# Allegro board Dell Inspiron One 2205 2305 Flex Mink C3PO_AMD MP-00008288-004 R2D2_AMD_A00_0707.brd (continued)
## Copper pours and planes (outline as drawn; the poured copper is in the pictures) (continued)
VDD_PCIE on BOTTOM: 56.02,153.42 55.64,153.8 53.73,153.8 53.73,156.21 51.57,158.37 51.57,160.34 52.08,160.85 52.78,160.85 54.37,159.26 54.37,158.12 56.4,156.08 56.4,155.57 56.91,155.07 56.91,154.31 57.41,153.8 57.41,153.54 57.29,153.42
VDD_PCIE on BOTTOM: 57.86,145.92 54.18,145.92 52.91,144.65 48.91,144.65 46.94,146.62 43.13,146.62 42.11,145.61 40.52,145.61 40.52,144.46 41.48,144.46 42.43,143.51 42.43,142.68 42.62,142.49 44.71,142.49 45.48,143.26 47.25,143.26 48.91,141.6 52.08,141.6 54.11,143.64 55.95,143.64 56.46,143.13 58.56,143.13 59.57,144.15 59.83,144.15 59.95,144.27 59.95,145.1 59.7,145.35 58.37,145.35 57.83,145.89 ; 1 cut-out
VDDA18PCIE on TOP: 61.06,129.91 61.48,129.49 61.48,128.02 60.44,126.97 59.8,126.97 59.64,127.14 59.64,129.71 59.84,129.91
VDDA18PCIE on TOP: 59.75,139.45 59.75,141.91 59.95,142.11 59.95,142.34 60.39,142.77 60.39,143.84 60.18,144.04 59.7,144.04 59.32,143.66 59.32,142.72 59.42,142.62 59.42,142.44 58.86,141.88 58.86,139.8 59.07,139.6 59.07,139.4 59.32,139.14 59.32,137.86 59.38,137.79 59.64,137.79 59.76,137.92 59.76,139.43
VDDA18PCIE on BOTTOM: 59.24,127.38 58.68,127.94 58.68,132.54 59.62,133.48 59.62,134.9 59.12,135.41 59.12,136.7 59.03,136.79 59.03,137.58 58.81,137.81 58.81,140.59 58.99,140.77 58.99,141.76 59.4,142.16 59.4,143.65 59.54,143.79 60.06,143.79 60.08,143.76 60.08,142.24 61.86,140.46 61.86,133.48 60.29,131.9 60.29,130.48 61.35,129.41 61.35,128.02 60.72,127.38
VDDAN_P1V1_CLK on TOP: 90.83,69.53 90.54,69.82 90.54,70.56 89.96,71.14 89.96,71.52 90.06,71.62 90.31,71.62 90.53,71.84 90.72,71.84 90.95,71.62 91.3,71.62 91.85,71.07 91.85,70.43 91.83,70.41 91.72,70.28 91.65,70.13 91.64,70.09 91.64,70.06 91.54,69.96 91.4,69.82 91.34,69.63 91.31,69.56 91.24,69.53
VDDAN_P1V1_CLK on TOP: 84.47,87.12 86.62,87.12 86.88,86.87 87.64,86.87 88.02,86.49 88.02,81.47 87.83,81.28 86.88,81.28 86.34,81.82 86.34,84.49 85.86,84.96 84.59,84.96 84.08,85.47 84.08,86.74
VDDAN_P1V1_CLK on BOTTOM: 86.18,85.47 86.18,84.71 86.69,84.2 86.69,82.49 87.07,82.11 87.83,82.11 88.02,82.3 88.02,84.26 88.21,84.45 88.21,84.96 88.02,85.15 88.02,85.22 87.58,85.66 86.37,85.66
VDDAN_P1V1_PCIE on TOP: 96.74,76.96 96.74,75.46 96.4,75.12 96.16,74.88 96.16,74.47 96.29,74.34 97.19,74.34 97.63,73.9 97.65,73.9 98.09,74.34 98.18,74.34 98.26,74.42 98.26,74.85 97.72,75.39 97.72,76.76 98.93,77.98 98.93,80.39 98.31,81.02 98.31,83.06 98.56,83.31 99.45,83.31 100.21,84.07 100.21,85.34 99.97,85.59 98.05,85.59 97.17,84.71 97.17,83.7 95.32,81.85 95.32,78.38
VDDAN_P1V1_PCIE on BOTTOM: 96.7,76.49 96.7,74.25 96.91,74.04 96.91,70.99 97.36,70.55 97.67,70.55 98.12,71 98.12,77.35 97.97,77.51 97.72,77.51
VDDAN_P1V1_SATA on TOP: 101.79,68.12 102.86,68.12 104.58,69.85 109.8,69.85 110.82,68.83 115.96,68.83 116.72,69.6 118.12,69.6 118.5,69.98 119.9,69.98 120.03,69.85 120.03,68.2 119.52,67.69 113.55,67.69 110.12,64.26 109.18,64.26 106.82,66.62 103.72,66.62 103.39,66.29 102.23,66.29 101.86,66.66 101.85,66.66 101.53,66.98 101.53,67.87
VDDAN_P3V3_USB_S on TOP: 78.57,74.42 83.09,69.9 87.06,69.9 87.74,69.21 87.77,69.21 87.9,69.08 87.9,68.9 87.87,68.86 87.76,68.71 87.72,68.53 87.13,67.94 81.8,67.94 80.4,69.34 80.4,69.98 80.15,70.23 77.86,70.23 77.73,70.36 77.73,72.01 76.59,73.15 75.96,73.15 75.83,73.28 75.83,74.17 76.08,74.42
VDDCR_P1V1 on VCC (solid shape): 97.42,69.01 97.42,68.62 97.36,68.5 97.36,64.59 96.64,63.88 93.75,63.88 93.18,64.45 91.97,64.45 91.9,64.53 91.9,65.45 92.4,65.96 92.4,66.72 92.67,66.99 93.56,66.99 94.31,67.74 94.31,68.19 94.83,68.71 95.28,69.15 97.28,69.15
VDDCR_P1V1 on BOTTOM: 93.53,64.26 93.26,64.53 93.26,67.41 93.67,67.82 94.31,67.82 94.63,68.14 95.58,68.14 96.02,68.58 96.02,69.34 96.15,69.47 96.72,69.47 96.91,69.28 96.91,68.58 97.05,68.44 97.94,68.44 98.12,68.25 98.12,66.16 98.27,66.02 98.27,65.22 98.12,65.08 97.43,65.08 97.19,64.84 97.19,63.84 96.98,63.63 96.06,63.63 95.42,64.26
VDDHTRX on TOP: 71.58,172.47 73.1,172.47 73.23,172.34 73.23,171.04 72.75,170.56 72.75,167.04 73.8,165.99 73.8,161.23 71,158.43 71,157.58 70.22,156.79 70.22,155.85 66.56,152.2 66.25,152.2 66.1,152.35 66.1,152.65 69.81,156.36 69.81,157.23 70.14,157.56 70.14,158.09 70.31,158.25 70.31,159.26 72.63,161.58 72.63,163.25 71.18,164.69 71.18,172.07
VDDHTTX on BOTTOM: 72.45,133.18 70.24,135.38 70.24,138.94 69.99,139.19 66.81,139.19 65.16,140.84 65.16,145.29 64.91,145.54 64.91,147.57 65.57,148.23 65.95,148.23 66.15,148.03 66.15,147.62 65.8,147.27 65.8,145.85 67.22,144.42 67.22,144.07 68.34,142.95 68.57,142.95 68.82,142.7 68.82,142.47 69.12,142.16 69.33,142.16 70.42,141.07 70.42,140.61 70.65,140.39 71.23,140.39 71.83,139.79 71.83,139.48 72.3,139.01 72.43,139.01 72.63,138.81 72.63,137.24 75.04,134.82 84.77,134.82 84.91,134.68 84.91,131.76 84.59,131.44 83.83,131.44 83.83,132.33 83.68,132.48 80.42,132.48 79.83,133.07 77.27,133.07 77.16,133.18
VDDIO_P3V3_GBE_S on TOP: 93.33,62.17 93.93,62.17 94.43,62.67 94.43,63.17 94.13,63.47 93.93,63.47 93.13,62.67 93.13,62.37
VDDIO_P3V3_S on TOP: 85.79,70.69 86.93,70.69 87.06,70.56 87.06,70.19 86.82,69.96 84.36,69.96 84.36,69.95 83.68,69.95 78.85,74.78 73.57,74.78 73.16,75.18 73.16,75.95 73.42,76.2 79.51,76.2 79.89,75.82 80.02,75.82 81.54,74.3 81.54,74.17 83.7,72.01 83.7,71.5 84.29,70.92 85.56,70.92
VDDPL_P3V3_SATA on TOP: 102.13,65.77 101.73,65.77 101.13,65.17 101.13,64.87 101.43,64.57 101.73,64.57 102.33,65.17 102.33,65.57
VDDPL_P3V3_USB_S on BOTTOM: 84.72,71.12 84.85,70.99 84.85,70.61 84.72,70.48 81.54,70.48 81.29,70.74 81.29,71.37 81.42,71.5 83.45,71.5 83.83,71.12
VIN_19 on TOP: 162.19,23.37 159.97,23.37 157.94,21.34 157.94,17.91 159.52,16.32 159.52,10.86 159.65,10.73 161.55,10.73 161.94,11.11 161.94,17.84 162.38,18.29 162.38,23.18
CLK_VDD on TOP (solid shape): 37.54,104.08 37.54,103 37.73,102.81 37.73,101.85 36.84,101.85 36.08,102.62 35.06,102.62 34.68,102.23 33.16,102.23 32.78,102.62 26.36,102.62 26.05,102.3 26.05,100.97 26.49,100.52 26.49,97.79 27.44,96.84 30.24,96.84 30.49,96.58 30.49,95.25 27.06,95.25 25.66,96.65 25.66,100.08 25.22,100.52 25.22,103.7 25.66,104.14 37.48,104.14
CPU_M_VREF_SUS on TOP (solid shape): 115.96,183.41 115.96,182.3 115.48,181.81 113.47,181.81 113.12,182.17 113.12,183.59 113.4,183.87 115.5,183.87
CPU_M_VREF_SUS on BOTTOM (solid shape): 115.96,183.54 115.96,179.91 115.71,179.65 115.05,179.65 114.87,179.83 114.87,181.58 114.73,181.72 113.74,181.72 113.35,182.12 113.35,183.41 113.75,183.82 115.68,183.82
CPU_VCORE on BOTTOM (solid shape): outline of 81 points within 123.88,142.3 126.97,160.75
CPU_VCORE on BOTTOM (solid shape): 113.18,159.49 113.25,159.47 113.38,159.33 113.38,158.81 114.27,157.92 114.27,157.67 113.38,156.78 113.38,156.27 114.16,155.49 114.16,155.01 113.38,154.24 113.38,153.73 114.27,152.84 114.27,152.59 113.38,151.7 113.38,151.19 114.18,150.39 114.18,149.96 113.38,149.16 113.38,148.65 114.27,147.76 114.27,147.51 113.38,146.62 113.38,146.11 114.19,145.3 114.19,144.89 113.26,143.95 112.24,143.95 111.86,144.33 111.26,144.33 111.22,144.37 111.22,145.78 111.26,145.86 111.34,145.88 111.98,146.36 111.34,146.84 111.26,146.87 111.22,146.94 111.22,148.32 111.26,148.4 111.34,148.42 111.96,148.76 111.62,149.38 111.6,149.39 111.57,149.42 111.31,149.42 111.31,150.85 111.34,150.92 111.42,150.94 111.98,151.48 111.34,151.92 111.26,151.95 111.22,152.02 111.22,153.4 111.26,153.48 111.34,153.5 111.98,153.98 111.34,154.46 111.26,154.49 111.22,154.56 111.22,155.94 111.26,156.02 111.34,156.04 111.98,156.52 111.34,157 111.26,157.03 111.22,157.1 111.22,158.52 111.26,158.55 111.48,158.55 111.54,158.55 111.86,158.55 112.48,159.18 112.5,159.18 112.67,159.23 112.82,159.33 112.97,159.38 113.11,159.47
CPU_VCORE on BOTTOM (solid shape): outline of 452 points within 116.3,142.3 121.89,160.97
CPU_VCORE on VCC (solid shape): 108.47,181.59 108.47,166.48 108.58,166.37 112.88,162.08 114.77,162.08 114.77,162.07 115.39,162.07 115.39,162.08 116.26,162.08 116.56,162.08 117.72,160.92 122.9,160.92 124.02,162.04 127.22,162.04 128.61,163.44 129.62,163.44 131.02,162.04 132.06,162.04 132.51,161.59 132.51,159.12 132.05,158.66 130.54,158.66 129.79,157.91 129.79,142.67 129.24,142.13 116.16,142.13 115.12,142.11 110.1,137.1 107.65,137.1 105.55,134.99 104.48,134.99 103.79,134.3 81.31,134.3 80.67,134.94 74.38,134.94 73.1,136.22 73.1,137.7 65.96,144.86 65.96,151.71 70.18,155.93 70.18,156.64 70.81,157.27 70.81,158.54 71.72,159.45 73.5,159.45 75.64,161.59 75.64,164.77 76.04,165.16 79.97,165.16 80.97,166.16 80.97,179.25 83.53,181.8 108.26,181.8
CPU_VCORE on TOP: 92.04,165.94 81.57,165.94 80.99,166.52 80.99,179.9 82.65,181.56 106.36,181.56 107.44,180.48 107.44,176.57 105.44,174.57 97.42,174.57 93.81,170.97 93.81,167.72
CPU_VCORE on BOTTOM: 80.85,177.5 80.85,178.94 83.39,181.48 103.01,181.48 103.52,180.97 103.52,177.61 102.63,176.72 101.42,176.72 94.82,170.12 94.82,166.69 93.99,165.86 82.43,165.86 81.37,166.93 81.37,169.8 81.82,170.26 81.82,176.52
CPU_VCORE on BOTTOM: 132.05,161.5 132.01,161.49 131.77,161.37 131.67,161.12 131.67,161.09 131.46,160.88 131.44,160.88 131.22,160.75 131.1,160.53 131.09,160.52 130.71,160.13 129.72,160.13 129.65,160.06 129.65,160.06 129.52,159.93 129.52,158.94 129.44,158.86 128.35,158.86 128.2,159.02 128.2,159.65 128.36,159.81 128.36,162.23 128.06,162.53 128.06,163.07 128.32,163.32 129.68,163.32 130.19,162.81 130.19,162.43 130.57,162.05 131.73,162.05 132.05,161.73
CPU_VCORE on INT1: 108.58,166.37 112.88,162.08 114.77,162.08 114.77,162.07 115.39,162.07 115.39,162.08 116.26,162.08 116.56,162.08 117.72,160.92 122.9,160.92 124.02,162.04 127.22,162.04 128.61,163.44 129.62,163.44 131.02,162.04 132.06,162.04 132.51,161.59 132.51,159.12 132.05,158.66 130.54,158.66 129.79,157.91 129.79,142.67 129.24,142.13 116.16,142.13 115.12,142.11 110.1,137.1 107.65,137.1 105.55,134.99 104.48,134.99 103.79,134.3 81.31,134.3 80.67,134.94 74.38,134.94 73.1,136.22 73.1,137.7 65.96,144.86 65.96,151.71 69.91,155.66 73.24,155.66 75.64,158.05 75.64,164.77 76.04,165.16 79.97,165.16 80.97,166.16 80.97,179.25 83.53,181.8 108.26,181.8 108.47,181.59 108.47,166.48 ; 1 cut-out
CPU_VDDA_RUN_OUT on TOP: 138.12,234.95 138.12,230.38 135.71,230.38 135.46,230.63 135.46,233.62 135.65,233.81 135.71,233.81 136.85,234.95
DCIN on VCC (solid shape): outline of 85 points within 143.33,4.7 149.17,14.92
DCIN on TOP: 144.73,4.83 143.84,5.71 136.54,5.71 134.63,7.62 134.63,10.67 136.15,12.19 137.68,12.19 138.06,12.57 138.06,14.1 138.31,14.35 141.49,14.35 141.74,14.1 143.9,14.1 144.98,15.18 146.46,15.18 147.34,16.06 147.34,17.64 146.12,18.86 146.12,21.46 148.22,23.56 152.41,23.56 153.68,24.83 157.24,24.83 157.24,20.07 156.98,19.81 154.95,19.81 153.76,18.62 153.76,16.94 152.66,15.85 152.66,13.78 152.28,13.4 150.7,13.4 150.38,13.08 150.38,8.32 150,7.94 150,6.16 148.66,4.83
DCIN on BOTTOM: 134.63,12.89 134.63,7.62 136.55,5.7 143.85,5.7 144.72,4.83 148.67,4.83 149.11,5.27 149.11,14.22 148.66,14.67 143.52,14.67 143.01,15.18 136.92,15.18
DCIN on INT1: 145.3,14.92 146.63,14.92 149.17,12.38 149.17,7.68 146.19,4.7 144.03,4.7 143.33,5.4 143.33,12.95
DDR3_P1V5_LL on TOP: 182.76,234.57 182.76,227.33 181.11,225.68 173.49,225.68 173.2,225.97 173.2,230.34 173.87,231.01 176.67,231.01 176.99,231.33 176.99,235.14 177.18,235.33 182,235.33
LAN_VDD10 on TOP: 128.41,23.88 129.36,22.92 132.15,22.92 135.24,26.01 135.24,31.41 135.71,31.88 135.71,34.99 135.46,35.24 133.87,35.24 130.95,32.32 130.95,26.92 130.31,26.29 129.3,26.29 128.92,26.67 128.92,29.21 129.49,29.78 129.49,32.26 129.68,32.45 129.68,33.66 129.61,33.72 128.92,33.72 128.28,34.35 128.28,35.75 127.07,36.96 121.74,36.96 121.42,36.64 121.42,35.31 121.61,35.12 122.82,35.12 122.82,35.88 122.95,36 126.5,36 127.2,35.31 127.2,33.85 127.52,33.53 127.52,32.7 126.5,31.69 126.5,31.11 126.63,30.99 126.95,30.99 127.26,31.31 127.77,31.31 128.03,31.05 128.03,29.97 127.65,29.59 127.07,29.59 126.82,29.34 126.82,28.83 127.14,28.51 127.14,27.3 125.8,25.97 119.64,25.97 119.39,26.23 119.39,27.18 119.64,27.43 119.64,29.19 118.62,30.21 117.98,30.21 117.74,29.97 117.74,28.19 117.93,28 117.93,24.95 118.46,24.42 120.49,24.42 121.03,23.88
LAN_VDD10 on BOTTOM: 133.93,40.39 133.93,34.04 134.12,33.85 135.77,33.85 136.28,34.35 136.28,40.13 135.58,40.83 134.38,40.83
LCDVCC on VCC (solid shape): 25.87,185.28 26.77,184.38 26.77,181.97 25.84,181.04 11.08,181.04 10.62,181.5 10.62,183.06 10.88,183.32 13.68,183.32 13.97,183.61 20.77,183.61 20.77,183.54 20.78,183.48 20.79,183.41 20.81,183.35 20.85,183.29 20.88,183.23 20.93,183.18 20.98,183.13 21.03,183.09 21.09,183.06 21.15,183.03 21.22,183.01 21.28,183 21.35,182.99 21.42,183 21.49,183.01 21.55,183.03 21.61,183.06 21.67,183.09 21.73,183.13 21.78,183.18 21.82,183.23 21.86,183.29 21.89,183.35 21.91,183.41 21.93,183.48 21.94,183.54 21.94,183.61 21.93,183.68 21.91,183.75 21.89,183.81 21.86,183.87 21.82,183.93 21.78,183.98 21.73,184.03 21.67,184.07 21.61,184.1 21.55,184.13 21.49,184.15 21.42,184.16 21.35,184.16 21.28,184.16 21.22,184.15 21.15,184.13 21.09,184.1 21.03,184.07 20.98,184.03 20.93,183.98 20.88,183.93 20.85,183.87 20.81,183.81 20.79,183.75 20.78,183.68 20.77,183.61 13.97,183.61 14.62,184.26 14.62,184.83 15.01,185.23 21.11,185.23 21.55,185.67 25.4,185.67
LCDVCC on TOP: 30.36,196.66 30.36,201.55 30.49,201.68 31.91,201.68 32.57,202.34 60.76,202.34 63.96,199.14 66.5,199.14 67,198.63 67,196.72 66.69,196.41 65.73,196.41 65.73,197.17 65.42,197.49 63.32,197.49 60.46,200.34 34.23,200.34 32.24,198.35 32.24,196.47 30.62,194.85 30.62,192.28 28.08,189.74 27.7,189.74 27.44,189.99 27.44,191.13 29.16,192.85 29.16,195.45
LCDVCC on TOP: 10.87,183.31 10.87,181.8 11.06,181.61 13.22,181.61 13.54,181.93 13.54,184.34 13.22,184.66 12.22,184.66
LCDVCC on TOP: 24.08,180.47 23.51,181.04 23.51,182.12 24.08,182.69 25.09,182.69 25.41,183.01 29.6,183.01 41.54,194.94 47.13,194.94 47.32,194.75 47.32,192.02 47.06,191.77 41.03,191.77 30.36,181.1 27.57,181.1 26.93,180.47
LCDVCC on BOTTOM: 25.16,181.1 26.93,182.88 26.93,183.51 23.89,183.51 23.6,183.23 23.6,182.85 22.68,181.93 22.68,181.23 22.81,181.1
LCDVCC on INT1: 23.51,183.13 23.51,180.97 23.89,180.59 24.39,180.59 26.17,182.37 26.17,183.51 29.22,186.56 29.22,191.9 28.84,192.28 28.59,192.28 27.19,190.88 27.19,186.82
LCDVCC_1 on TOP: 7.63,186.69 7.63,185.67 8.01,185.29 13.09,185.29 14.23,186.44 14.23,187.96 13.98,188.21 9.15,188.21
LCDVCC_MXM on TOP: 25.09,203.39 27,203.39 27.44,202.95 31.38,202.95 31.51,202.82 31.51,202.31 31.25,202.06 30.24,202.06 29.98,201.8 29.98,198.5 29.86,198.37 28.33,198.37 28.08,198.63 28.08,199.77 27.19,200.66 25.03,200.66 24.9,200.79 24.9,203.2
LCDVCC_NB on TOP: 65.67,195.83 67.32,195.83 67.45,195.71 72.85,195.71 72.85,194.82 71.51,194.82 71,194.31 71,191.9 70.75,191.64 65.8,191.64 65.42,192.02 65.42,195.58
NB_VDDHT on TOP: 78.69,171.96 78.69,168.31 78.62,168.25 77.48,168.25 76.64,169.09 76.64,170.17 76.69,170.21 76.69,171.99 76.85,172.15 78.5,172.15
NB_VDDHT on BOTTOM: 70.42,156.11 70.42,156.01 67.4,152.98 67.35,152.98 67.19,152.83 67.19,152.3 67.07,152.17 66.28,152.17 66.05,151.94 66.05,151.61 66.43,151.23 66.43,150.16 66.33,150.06 65.01,150.06 64.86,150.22 64.86,151.56 66.3,153.01 66.3,153.52 67.02,154.23 67.3,154.23 68.18,155.12 68.18,155.93 68.95,156.69 69.84,156.69
USB5V2 on TOP: 13.73,99.44 13.73,97.32 10.3,93.89 10.3,92.04 13.73,88.62 13.73,81.92 13.09,81.28 13.09,77.72 13.6,77.22 16.01,77.22 16.39,77.6 16.39,82.23 18.93,84.77 18.93,97.92 16.77,100.08 14.36,100.08
USB5V2 on BOTTOM: 10.3,99.44 10.3,98.3 11.19,97.41 11.19,94.87 10.3,93.98 10.3,91.5 10.62,91.19 12.58,91.19 12.71,91.31 12.71,97.66 13.73,98.68 14.55,98.68 14.55,99.5 14.11,99.95 10.81,99.95
USB5V2 on BOTTOM: 10.68,80.01 13.73,80.01 14.49,80.77 16.01,80.77 16.39,80.39 16.39,78.74 17.73,77.41 17.73,75.63 17.03,74.93 17.03,72.58 17.28,72.33 17.28,72.01 17.16,71.88 16.97,71.88 16.33,72.52 15.44,72.52 15.25,72.71 15.25,75.37 14.81,75.82 14.81,76.73 14.55,76.99 11.8,76.99 10.42,78.36 10.42,79.76
V_AMP on TOP: 19.31,36.07 19.44,36.2 20.58,36.2 20.71,36.32 20.71,37.47 20.01,38.16 18.24,38.16 17.41,37.34 16.14,37.34 16.14,36.39 16.46,36.07
V_AMP on BOTTOM: 20.71,36.83 20.71,37.85 19.44,39.12 18.16,39.12 17.93,39.34 16.22,39.34 15.81,38.94 14.9,38.94 14.7,38.74 14.7,38.08 14.94,37.85 18.17,37.85 18.81,37.21 19.44,37.21 19.82,36.83
VLDT_P1V2 on TOP (solid shape): 117.31,102.41 117.31,101.12 117.03,100.84 114.08,100.84 113.7,101.22 113.7,102.29 114.03,102.62 117.1,102.62
VLDT_P1V2 on BOTTOM: 88.89,131.93 91.04,131.93 91.58,131.39 91.58,127.83 91.26,127.51 91.26,127 91.01,126.75 89.8,126.75 89.67,126.62 88.66,126.62 88.66,131.7
N185693726 on BOTTOM: 16.39,35.31 16.52,35.43 16.52,36.32 16.93,36.73 17.64,36.73 17.79,36.58 17.79,35.69 18.07,35.69 18.07,36.58 18.15,36.65 18.35,36.65 18.43,36.58 18.43,35.69 18.73,35.69 18.73,36.91 18.04,37.59 16.14,37.59 15.5,36.96 15.5,35.69 15.89,35.31
N185693750 on BOTTOM: 18.73,29.84 18.73,28.5 18.04,27.81 16.14,27.81 15.89,27.56 15.63,27.56 15.63,28.19 16.27,28.83 17.66,28.83 17.79,28.96 17.79,29.84 18.07,29.84 18.07,28.93 18.17,28.83 18.32,28.83 18.43,28.93 18.43,29.84
N192917727 on BOTTOM: 152.41,19.62 152.41,17.53 152.73,17.21 154.51,17.21 155.59,18.29 156.09,18.29 156.28,18.48 156.28,19.56 155.46,20.38 153.17,20.38
N192922009 on TOP: 100.46,195.58 104.79,195.58 105.39,194.98 105.39,192.63 106.19,191.83 109.74,191.83 109.74,190.56 107.42,188.25 107.42,186.47 106.63,185.67 100.66,185.67 99.96,186.37 99.96,195.07 100.45,195.56
N192922293 on TOP: 96.31,192.16 96.47,192 96.47,189.87 97.36,188.98 97.36,186.12 96.66,185.42 88.02,185.42 86.75,186.69 86.75,195.33 87.1,195.68 91.58,195.68 91.83,195.42 91.83,192.85 92.53,192.16
N192994201 on TOP (solid shape): 122.38,219.58 122.38,216.98 123.2,216.15 126.88,216.15 126.88,210.88 125.93,209.93 117.87,209.93 116.85,210.95 116.85,220.01 121.94,220.01
N193056406 on TOP (solid shape): 178.95,29.97 178.95,25.27 177.94,24.26 176.54,24.26 174.76,22.48 169.43,22.48 169.05,22.86 169.05,24.13 168.67,24.51 168.16,24.51 168.03,24.64 168.03,25.27 168.29,25.53 172.22,25.53 172.73,26.04 175.91,26.04 176.41,26.54 176.41,28.57 175.65,29.34 174.51,29.34 174.51,30.1 173.49,31.11 171.97,31.11 171.97,33.78 175.14,33.78
N193056406 on BOTTOM: 170.25,22.67 170.25,24.38 171.91,26.04 175.91,26.04 176.41,26.54 176.41,28.57 175.91,29.08 174.64,29.08 174.38,29.34 174.38,30.35 175.02,30.99 177.94,30.99 178.95,29.97 178.95,24.38 177.68,23.11 174.13,23.11 173.24,22.23 170.7,22.23
N193056421 on TOP (solid shape): 192.03,28.07 192.03,17.02 191.4,16.38 187.08,16.38 186.57,16.89 186.57,19.56 185.99,20.14 182.44,20.14 182.26,20.32 182.26,24.51 182.32,24.57 182.32,28.89 183.14,29.72 190.38,29.72
N193057155 on TOP (solid shape): 172.48,28.45 172.48,26.29 172.1,25.91 168.03,25.91 167.27,25.15 167.27,21.72 166.38,20.83 165.68,20.83 164.98,21.53 164.98,23.5 164.48,24 159.65,24 158.89,24.77 158.89,28.32 159.4,28.83 172.1,28.83
N193073757 on BOTTOM (solid shape): 176.41,236.73 176.41,232.03 175.91,231.52 165.62,231.52 164.48,232.66 164.48,234.7 165.24,235.46 171.08,235.46 171.33,235.71 171.33,236.73 171.97,237.36 175.78,237.36
N193073757 on TOP: 163.59,231.9 163.59,234.19 164.86,235.46 171.08,235.46 171.33,235.71 171.33,236.47 171.65,236.79 175.65,236.79 176.34,236.11 176.34,231.95 175.91,231.52 163.97,231.52
N193081910 on TOP: 149.74,46.1 143.14,46.1 142.02,44.98 142.02,40.42 142.26,40.18 142.85,40.18 143.1,40.42 143.1,41.73 143.4,42.04 144.66,42.04 145.17,41.53 150.51,41.53 151.01,42.04 151.01,44.83
N193081924 on TOP: 137.68,49.58 137.68,48.64 137.04,48.01 132.98,48.01 132.6,47.62 132.47,47.62 132.47,50.67 131.84,51.31 131.84,52.96 132.47,53.59 139.13,53.59 139.58,53.14 139.58,51.49
N193082210 on TOP: 133.87,46.23 133.87,41.53 134.5,40.89 137.55,40.89 138.82,42.16 140.35,42.16 140.65,41.87 140.65,40.55 140.99,40.21 141.5,40.21 141.74,40.45 141.74,46.61 141.11,47.24 134.88,47.24
N193554651 on TOP: 65.42,18.54 65.8,18.16 70.94,18.16 71.45,18.67 71.45,20.7 71.7,20.95 73.48,20.95 73.48,24 73.23,24.26 64.02,24.26 63.89,24.13 63.89,21.34 65.42,19.81
N203761921 on TOP: 73.92,12.19 74.31,12.57 76.08,12.57 76.85,11.81 76.85,10.79 76.21,10.16 75.32,10.16 75.19,10.03 75.19,9.4 75.07,9.27 74.05,9.27 73.92,9.4
N203766757 on TOP: 46.87,11.94 48.4,11.94 48.91,11.43 48.91,10.54 49.29,10.16 49.54,10.16 49.79,9.91 49.79,9.27 49.54,9.02 48.78,9.02 48.4,8.64 48.4,7.49 48.02,7.11 47,7.11 46.62,7.49 46.62,11.68
N204331890 on TOP: 78.73,107.7 78.73,109.45 79.26,109.98 81.67,109.98 81.8,110.11 81.8,112.78 79,112.78 78.88,112.9 75.07,112.9 74.81,113.16 74.81,114.24 74.22,114.83 69.63,114.83 68.59,113.79 68.59,109.86 70.11,108.33 77.35,108.33 77.99,107.7
N204331927 on TOP: 81.56,109.21 81.42,109.35 79.39,109.35 79.39,106.93 78.24,105.79 78.24,104.01 77.99,103.76 77.99,102.11 78.24,101.85 80.91,101.85 81.16,102.11 81.16,104.19 82.05,105.08 82.05,107.25 81.56,107.75
N204331927 on BOTTOM: 77.54,107.26 77.54,106.11 79.64,104.01 81.01,104.01 81.88,104.88 82.89,104.88 82.89,107.21 81.77,107.21 81.72,107.26
N205761415 on TOP: 80.1,117.37 80.1,121.51 81.05,122.47 81.05,127.5 80.66,127.89 78.4,127.89 77.35,126.85 77.35,117.4 77.56,117.2 79.92,117.2
N205761421 on BOTTOM (solid shape): 81.37,116.41 81.37,115.77 82.05,115.09 82.59,115.09 82.75,114.92 82.75,113.3 82.64,113.18 81.09,113.18 80.43,113.84 80.43,116.46 80.5,116.54 81.24,116.54
N205761421 on TOP: 80.48,117.22 80.48,121.46 80.77,121.75 82.57,121.75 83.73,120.6 83.73,116.71 85.2,115.24 90.77,115.24 91.6,114.4 92.77,114.4 92.95,114.22 92.95,113.26 92.85,113.16 81.11,113.16 80.43,113.84 80.43,115.14 80.45,115.16 80.45,117.2
N209450511 on TOP (solid shape): 50.56,195.14 52.14,195.14 52.27,195.01 52.27,192.02 50.68,192.02 50.68,193.74 50.43,193.99 49.22,193.99 49.03,194.18 49.03,195.07 49.16,195.2 50.49,195.2
N228109241 on TOP: 74.05,202.31 74.05,201.68 74.69,201.04 76.46,201.04 76.46,201.93 75.07,201.93 74.69,202.31
N229090690 on BOTTOM: 12.65,72.64 12.65,75.31 12.96,75.63 14.43,75.63 14.74,75.31 14.74,72.83 14.43,72.52 12.77,72.52

Small or netless copper shapes (teardrops, artwork), in the pictures only: 201 on TOP, 13 on BOTTOM

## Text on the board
Ref Des/Silkscreen Bottom: AOI LABEL | E315671 | MP-00008289-004
User.Comments: 9. | 10. | 11. | 12. | 13. | 14. | 15. | 16. | 17. | 18. | 19. | 1. | 2. | 3.The stack up 6 layer | 21. | 20. | 6. | 7. | 8. | 4. | 5. | PCB SAMPLE 2 pcs ,TEST REPORT AND DRAWING WILL FEEDBACK TO TAIWAN EE Engineer | PCB Size:196.1mm X 255mm | All via are cover with soldermask(double side) | Tset point are cover with soldermask(single side) | (   Include V-CUT    Don't Inculde V-CUT) | DATE CODE INDICATION: | UL MARK: | UL MARK NO: | VENDOR LOGO: | MANUFACTURING ORIGIN:(MADE IN China): | DRAWING FORMAT: | COPPER PLATING THICKNES: | GOLD FINGER THICKNESS(uM): | WARP/TWIST:+/-0.7% PER LINEAE INCH. | IMPEDANCE CONTROL: | signal ended and differential impedance control please sees above table. | a.PCB STACK-UP CONSTRUCTION CAN BE MODIFIED WITH FLEXTRONICS APPROVAL | b.TYPICAL TRACE WIDTH=4.0MIL 60ohm +/-15% MICROSTRIP | c.CORE MATERIAL IS 1080 FR4 | d.PCB MUST CONFORM TO UL796 | e.PCB MUST BE UL RECOGNIZED | f.PCB MUST BE UL 94V-0 FLAMMABILITY RATING | PCB SILKSCREEN: | PCB SOLDERMASK: | Name | BOT | OTHER NOTES: | -APPROVAL REPORT MUST INCLUDE THE | MICRO-SECTION REPORT AND IMPEDANCE | -VENOR MUST REMARK DATE ON PACKING | SLIP, INCLUDING THE VENDOR, PRODUCT | ECTH AND DRILL: | Plate (BOARD NEED PB FREE) | TOP | PLEASE PUT ALL IMPEDANCE TEST CUPON ON THE V-CUT,INCLUDE DIFF PAIR AND SIGLE END | CUPON BOARD NEED FEEBACK TO TAIWAIN CSDC | Address:5F.,No.6,Sec.1,Jhongsing Rd., Wugu Township,Taipei County 248,Taiwan,R.O.C | NEED DETAIL IMPEDANCE REPPORT FOR ALL OF TRACES | GND1 | VCC | INT1 | GND2 | layer | -PTH:+/-0.003         -NPTH:+/-0.002 | -0.001"PLATING IN THE PTH HOLE MIN | A.MINIMUM TRACE WIDTH=3.5MIL | B.MINIMUM SPACING=4MILS | YYWW | NEED | NO NEED | White | Green | ECTH BOTTOM | TEST REPORT.(IF H.A.S.L BEFORE PLUG | MUST INCLUDE THE VIA MICRO-SECTION). | NAME,REV,DATE | ADD V-CUT: | PCB BOARD: | PCB FILM: | C.MINIMUM DRILL=10MILS | D.SPECIAL DRILL | OSP | BOTH | Plane Description | Total thickness | Yellow | WWYY | 15-20 | solder mask | prepreg | ImAg | SIGNAL | CORE | GND | VDD | ECTH TOP | Blue | OVER 30 | UPPER | ImSn | Single | Differential | Device | Other | Red | UNDER | ENIG | thickness | 0.65 | 2 | 4 | 1.2 | 36 | (mil) | Breakout | width/spacing/width/to others spaing | Outer Layer | Inner Layer | 62.1mil+10mil/-10mil | 0.5+plating | 1.0 | weight | Copper | (oz) | Dielectric | 3.9/4 mils | 3.5/4 mils | 3.9/4/3.9/6 mils | 3.5/4/3.5/6 mils | Er | 3.8 | 3.6 | 4.5 | Tolerance | +/- 1 | width/spacing/width | 6/5.5/6 mils | 5.1/5.6/5.1 mils | 5/6.2/5 mils | 3.9/6.1/3.9 mils | 5/5.5/5 mils | 4.1/5/4.1 mils | 4/5.5/4 mils | 3.5/6/3.5 mils | Trace Width | 6.5 mils | 5.1 mils | 4 mils | 5.6 mils | 4.5 mils | 3.5ils | 11.2 mils | 9 mils | 9.8 mils | 8.5 mils | 12.6 mils | 11 mils | Field-solved impedances,Outerlayers | Field-solved impedances,Innerlayers | 85-diff. ohms | 90-diff. ohms | 93-diff.ohms | 100-diff.ohms | 37.5 ohms | 40 ohms | 50 ohms | 55 ohms | 60 ohms | 35 ohms | Impedance | Variation | 15% | 10% | SATA-CAL | VGA | DDR3-CTRL,DDR3-CMD,DDR3-DQ | PCIe2,DMI,DDR3-DQS,USB,LVDS,SDVO,HDMI,FDI,Display Port | SATA,CLK-DIFF | HT | LAN | DEFAULT,CLOCK-SINGLE | CLOCK-SINGLE | Bus | THIS DRAWING CONTAINS INFORMATION PROPRIETARY TO FLEXTRONICS | AND SHALL NOT BE USED IN WHOLE OR IN PART WITHOUT CONSENT. | CUSTOMER: | SCHEMATIC DSN FILENAME: | ALLEGRO BRD FILENAME: | DRAWN BY | DESIGN | PROJECT | CUSTOMER DESCRIPTION: | REV | DATE | DESCRIPTION | CUSTOMER PART NUMBER: | APPROVED | Wells Yu | MIL(1/1000INCH) | DIMENSIONS ARE IN: | Dells | MINK_AMD_A00_P012_0707_1540.dsn | MINK_AMD_A00_P012_0707_1700.brd | Porter Chen | MINK | X00 | V01 | X01 | A00 | 07-July-10 | REVISIONS | P/N | 08-Feb-10 | 26-Mar-10 | 23-Apr-10 | 04-June-10 | Porter | SIZE | TITLE | SCALE: | PART NO. | SHEET | OF | REV: | 1/1 | XXX | A1 | D | C | B | A | 8 | 7 | 6 | 5 | 3 | 1
Ref Des/Silkscreen Top: AMI LABEL | 1 | P/N LABEL | MP-00008288-004 | CIR Receiver | PPID LBL | MAC LABEL | S/N LABEL | CIR Emitter | HP | MIC IN | Vol+ | Vol- | WLAN\COMBO | * | AV IN_NB | LVDS_NB | BT | Line Out | MXM FAN | HDD PWR | CPU FAN | TV TUNER | LVDS_MXM | AV IN_MXM | Touch | DIMM_1 | ODD PWR | DIMM_2 | SYS FAN | C | B | E | X | HDD | ODD | PCB ver.A00
GND1: GND1 PLANE(LAYER:02)
INT1: INT1 PLANE(LAYER:03) | p1v5 | GND | P5V | p1v1 | p5v_usb | gnd | P19v_filt | cpu_vcore | dcin | p5v_stby | p19v_sys | p1v5_cpu_vddio_sus | p1v2_cpu_vddr | p1v2_cpu_vddnb_run
User.5: FIGURE | SIZE | 0.8 | 0.9 | 1.3 | 1.4 | 1.5 | 1.6 | 10.0 | 12.0 | 26.0 | 28.0 | 30.0 | 31.0 | 33.0 | 35.0 | 41.0 | 43.0 | 44.0 | 47.0 | 53.0 | 55.0 | 63.0 | 81.0 | 91.0 | 96.0 | 118.0 | 0.3 | 1.1 | 22.0 | 39.0 | 51.0 | 146.0 | 154.0 | 161.0 | DRILL CHART: TOP to BOTTOM | ALL UNITS ARE IN MILS | PLATED | NON-PLATED | QTY | 1 | 6 | 2 | 1284 | 3391 | 480 | 14 | 36 | 44 | 80 | 24 | 21 | 8 | 18 | 4 | 12 | 3
User.15: 39x124 | 24x59 | 47x131 | 59x24 | 100x39 | 71x26 | 26x71 | 39x81
User.18: PANEL DWG,M/B,MINK_AMD_C3PO,VER.X00,6L,OSP | PANEL DWG,M/B,MINK_AMD_C3PO,VER.X01,6L,OSP | PANEL DWG,M/B,MINK_AMD_C3PO,VER.A00,6L,OSP | PANEL DWG,M/B,SOLO,VER.X00,4L,OSP | PANEL DWG,M/B,SOLO,VER.X01,6L,OSP | MP-00008288-004-AV | 1
User.19: PLACEMENT DWG,M/B,MINK_AMD_C3PO,VER.X00,6L,OSP | PLACEMENT DWG,M/B,MINK_AMD_C3PO,VER.X01,6L,OSP | PLACEMENT DWG,M/B,MINK_AMD_C3PO,VER.A00,6L,OSP | PCBA,M/B,SOLO,VER.X00 | PCBA,M/B,SOLO,VER.V01 | MP-00008288-004-AE | 1 | 2
User.20: PLACEMENT DWG,M/B,MINK_AMD_C3PO,VER.A00,6L,OSP | PLACEMENT DWG,M/B,MINK_AMD_C3PO,VER.X01,6L,OSP | PLACEMENT DWG,M/B,MINK_AMD_C3PO,VER.X00,6L,OSP | PCBA,M/B,SOLO,VER.X00 | PCBA,M/B,SOLO,VER.V01 | MP-00008288-004-AE | 2
User.21: TP TOP
User.22: TP BOTTOM
User.27: 1 | 2 | 51 | 52
User.29: vddcr_p1v1 | p1v5 | vdd_pcie | lcdvcc | p3v3 | p1v8 | p5v_stby | p1V25 | GND | p5v | p3v3_stby | gnd | P19v_filt | p3v3_sb | cpu_vcore | p19v_sys | dcin | p1v5_cpu_vddio_sus | p1v2_cpu_vddnb_run
User.30: gnd_audio | gnd | p1v5_cpu_vddio_sus
User.39: DESIGNED BY | FLEXComputing TAIWAN | TAIPEI CSDC | TEL:886-2-8977-1888 | UNLESS OTHERWISE | SPECIFIED DIMENSIONS | ARE IN MILS | DESIGNER: | PROJECT NAME: | LAYOUT BY: | NAME | Wells Yu | MINK | DATE: | 2010.06.04 | REV: | X01 | GND1 PLANE(LAYER:02) | FLEXTRONICS
User.40: DESIGNED BY | FLEXComputing TAIWAN | TAIPEI CSDC | TEL:886-2-8977-1888 | UNLESS OTHERWISE | SPECIFIED DIMENSIONS | ARE IN MILS | DESIGNER: | PROJECT NAME: | LAYOUT BY: | NAME | Wells Yu | MINK | DATE: | 2010.06.04 | REV: | X01 | INT1 PLANE(LAYER:03) | FLEXTRONICS
User.41: DESIGNED BY | FLEXComputing TAIWAN | TAIPEI CSDC | TEL:886-2-8977-1888 | UNLESS OTHERWISE | SPECIFIED DIMENSIONS | ARE IN MILS | DESIGNER: | PROJECT NAME: | LAYOUT BY: | NAME | Wells Yu | MINK | DATE: | 2010.06.04 | REV: | X01 | VCC PLANE(LAYER:04) | FLEXTRONICS
User.42: DESIGNED BY | FLEXComputing TAIWAN | TAIPEI CSDC | TEL:886-2-8977-1888 | UNLESS OTHERWISE | SPECIFIED DIMENSIONS | ARE IN MILS | DESIGNER: | PROJECT NAME: | LAYOUT BY: | NAME | Wells Yu | MINK | DATE: | 2010.06.04 | REV: | X01 | GND PLANE(LAYER:05) | FLEXTRONICS
User.43: DESIGNED BY | FLEXComputing TAIWAN | TAIPEI CSDC | TEL:886-2-8977-1888 | UNLESS OTHERWISE | SPECIFIED DIMENSIONS | ARE IN MILS | DESIGNER: | PROJECT NAME: | LAYOUT BY: | NAME | Wells Yu | MINK | DATE: | 2010.06.04 | REV: | X01 | SOLDER SIDE | FLEXTRONICS
User.44: DESIGNED BY | FLEXComputing TAIWAN | TAIPEI CSDC | TEL:886-2-8977-1888 | UNLESS OTHERWISE | SPECIFIED DIMENSIONS | ARE IN MILS | DESIGNER: | PROJECT NAME: | LAYOUT BY: | NAME | Wells Yu | MINK | DATE: | 2010.04.23 | REV: | X00 | TP BOTTOM | FLEXTRONICS
User.45: DESIGNED BY | FLEXComputing TAIWAN | TAIPEI CSDC | TEL:886-2-8977-1888 | UNLESS OTHERWISE | SPECIFIED DIMENSIONS | ARE IN MILS | COMPONENT SIDE | DESIGNER: | PROJECT NAME: | LAYOUT BY: | TP TOP | NAME | Wells Yu | MINK | DATE: | 2010.04.23 | 2010.06.04 | REV: | X00 | X01 | FLEXTRONICS
